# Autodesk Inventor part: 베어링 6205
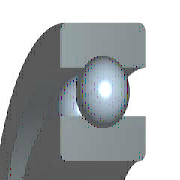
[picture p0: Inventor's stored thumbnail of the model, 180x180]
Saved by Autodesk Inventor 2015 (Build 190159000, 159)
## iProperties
Created: 2015-10
Part Number: 베어링 6205
Material: 강, 연강
Description: 깊은 그루브 볼 베어링
Document SubType Name: Modeling
Standard: KS B 2023
Designer: mdu
Standards Organization: KS
Language: ko-KR
Size Designation: 6205 - 25 x 52 x 15
Categories: <MemberInstance><Categories><Category DisplayName="샤프트 부품" InternalName="7f7aeb1f-a693-4053-b835-cee3144e0d98" Mnemonic="SHFT"><Category DisplayName="베어링" Inter
Density: 1 g/cm^3
Appearance: 강철
IsCustomPart: 1
Author: mdu
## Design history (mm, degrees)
sketch "스케치" dims "d0" = 7.02 (= -0.26 x WD + 0.26 x BD)
  geometry: L1 (3.99, 19.25)-(11.01, 19.25); L2 (7.5, 19.25)-(7.5, 15.74); L3 (7.5, 19.25)-(7.5, 22.76); L4 (4.892, 16.901)-(0, 16.901); L5 (0, 12.5)-(15, 12.5); L6 (4.892, 21.599)-(0, 21.599); L7 (0, 26)-(15, 26); L8 (15, 12.5)-(15, 16.901); L9 (10.108, 16.901)-(15, 16.901); L10 (10.108, 21.599)-(15, 21.599); L11 (15, 26)-(15, 21.599); L12 (-1.4, 0)-(8.4, 0) reference; L13 (0, -0.3)-(0, 5.3) reference
  constraints: 22 end point, 4 point on line, 2 collinear, 2 perpendicular, 2 symmetric about line, 1 midpoint, 1 parallel, 14 other
  dimensions: "d9" = 25 diameter of L5 L12 (= WD); "d11" = 52 diameter of L7 L12 (= BD); "d12" = 15 distance between parallel lines of L8 L13 (= KB); "d13" = 33.802 diameter of L9 L12 (= 0.326 x BD + 0.674 x WD)
revolve "본체" stored, may be unused: angle "d6" = 90 deg
revolve "볼" stored, may be unused: angle "d7" = 90 deg
pattern_circular "IDS_ARRAYBALL[SIMPL:T]" dims angle "d3" = 360 deg
body "Solid1"
fillet "모깎기1" dims "d1" = 1 (= KRS)
other parameters: "WD" = 25 [user parameter; used in 5 equation terms], "BD" = 52 [user parameter; used in 5 equation terms], "KB" = 15 [user parameter; used in 1 equation term], "KRS" = 1 [user parameter; used in 1 equation term], "d4" = 0, "d5" = 0, "d8" = 0, "d14" = 0, "d15" = 0, "BBA" = 0 [user parameter], "BC0" = 7800000 [user parameter], "BC" = 1.4e+07 [user parameter], "BR" = 26 (= 0.5 x BD) [user parameter], "WR" = 12.5 (= 0.5 x WD) [user parameter]
